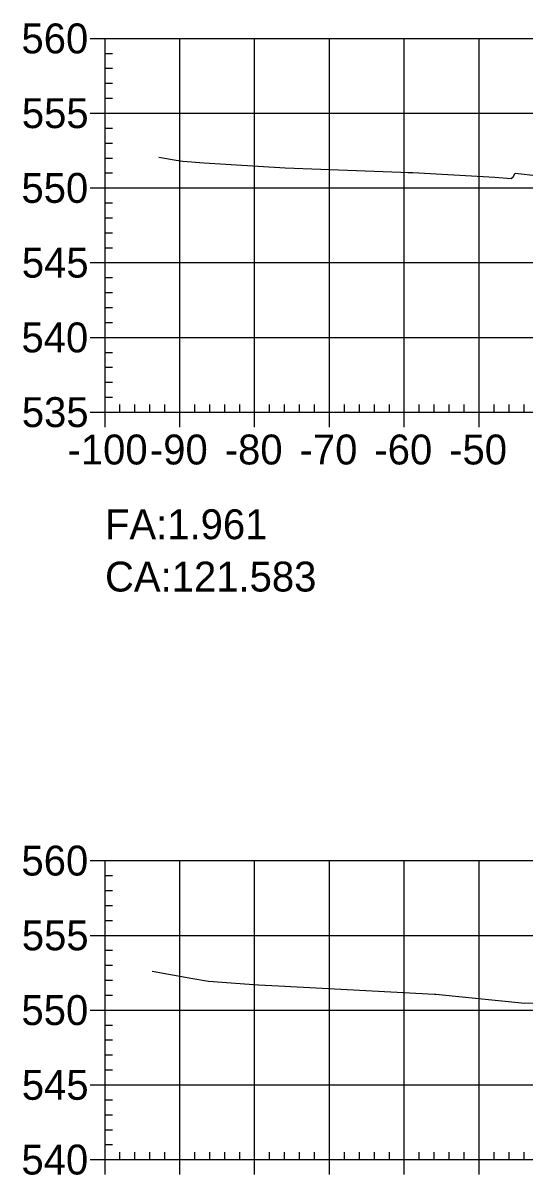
# Model space of a CAD drawing. Extents: x 704834 to 709892, y 372981 to 377533.
# Drawn here: x 707125.9 to 707193, y 373740.8 to 373894.9 of the extents above; entities that cross this region are included whole.
import ezdxf

# ---------------------------------------------------------------- set-up
doc = ezdxf.new("R2010")
doc.units = 0
for name, color, linetype in [('57', 7, 'Continuous'), ('59', 7, 'Continuous'), ('Existing', 7, 'Continuous')]:
    doc.layers.add(name, color=color, linetype=linetype)

msp = doc.modelspace()

# ---------------------------------------------------------------- linework, layer by layer
at = {"layer": '57'}
for p, q in [((707134.87, 373892.82), (707136.87, 373892.82)), ((707136.87, 373892.82), (707336.87, 373892.82)), ((707136.87, 373842.82), (707136.87, 373892.82)), ((707136.87, 373842.82), (707136.87, 373892.82)), ((707146.87, 373842.82), (707146.87, 373892.82)), ((707156.87, 373842.82), (707156.87, 373892.82)), ((707166.87, 373842.82), (707166.87, 373892.82)), ((707176.87, 373842.82), (707176.87, 373892.82)), ((707186.87, 373842.82), (707186.87, 373892.82)), ((707136.87, 373890.82), (707137.87, 373890.82)), ((707136.87, 373888.82), (707137.87, 373888.82)), ((707136.87, 373886.82), (707137.87, 373886.82)), ((707136.87, 373884.82), (707137.87, 373884.82)), ((707134.87, 373882.82), (707136.87, 373882.82)), ((707136.87, 373882.82), (707336.87, 373882.82)), ((707136.87, 373880.82), (707137.87, 373880.82)), ((707136.87, 373878.82), (707137.87, 373878.82)), ((707136.87, 373876.82), (707137.87, 373876.82)), ((707136.87, 373874.82), (707137.87, 373874.82)), ((707134.87, 373872.82), (707136.87, 373872.82)), ((707136.87, 373872.82), (707336.87, 373872.82)), ((707136.87, 373870.82), (707137.87, 373870.82)), ((707136.87, 373868.82), (707137.87, 373868.82)), ((707136.87, 373866.82), (707137.87, 373866.82)), ((707136.87, 373864.82), (707137.87, 373864.82)), ((707134.87, 373862.82), (707136.87, 373862.82)), ((707136.87, 373862.82), (707336.87, 373862.82)), ((707136.87, 373860.82), (707137.87, 373860.82)), ((707136.87, 373858.82), (707137.87, 373858.82)), ((707136.87, 373856.82), (707137.87, 373856.82)), ((707136.87, 373854.82), (707137.87, 373854.82)), ((707134.87, 373852.82), (707136.87, 373852.82)), ((707136.87, 373852.82), (707336.87, 373852.82)), ((707136.87, 373850.82), (707137.87, 373850.82)), ((707136.87, 373848.82), (707137.87, 373848.82)), ((707136.87, 373846.82), (707137.87, 373846.82)), ((707136.87, 373844.82), (707137.87, 373844.82)), ((707138.87, 373842.82), (707138.87, 373843.82)), ((707140.87, 373842.82), (707140.87, 373843.82)), ((707142.87, 373842.82), (707142.87, 373843.82)), ((707144.87, 373842.82), (707144.87, 373843.82)), ((707148.87, 373842.82), (707148.87, 373843.82)), ((707150.87, 373842.82), (707150.87, 373843.82)), ((707152.87, 373842.82), (707152.87, 373843.82)), ((707154.87, 373842.82), (707154.87, 373843.82)), ((707158.87, 373842.82), (707158.87, 373843.82)), ((707160.87, 373842.82), (707160.87, 373843.82)), ((707162.87, 373842.82), (707162.87, 373843.82)), ((707164.87, 373842.82), (707164.87, 373843.82)), ((707168.87, 373842.82), (707168.87, 373843.82)), ((707170.87, 373842.82), (707170.87, 373843.82)), ((707172.87, 373842.82), (707172.87, 373843.82)), ((707174.87, 373842.82), (707174.87, 373843.82)), ((707178.87, 373842.82), (707178.87, 373843.82)), ((707180.87, 373842.82), (707180.87, 373843.82)), ((707182.87, 373842.82), (707182.87, 373843.82)), ((707184.87, 373842.82), (707184.87, 373843.82)), ((707188.87, 373842.82), (707188.87, 373843.82)), ((707190.87, 373842.82), (707190.87, 373843.82)), ((707192.87, 373842.82), (707192.87, 373843.82)), ((707134.87, 373842.82), (707136.87, 373842.82)), ((707136.87, 373842.82), (707336.87, 373842.82)), ((707136.87, 373842.82), (707336.87, 373842.82)), ((707136.87, 373840.82), (707136.87, 373842.82)), ((707146.87, 373840.82), (707146.87, 373842.82)), ((707156.87, 373840.82), (707156.87, 373842.82)), ((707166.87, 373840.82), (707166.87, 373842.82)), ((707176.87, 373840.82), (707176.87, 373842.82)), ((707186.87, 373840.82), (707186.87, 373842.82)), ((707134.87, 373782.82), (707136.87, 373782.82)), ((707136.87, 373782.82), (707336.87, 373782.82)), ((707136.87, 373742.82), (707136.87, 373782.82)), ((707136.87, 373742.82), (707136.87, 373782.82)), ((707146.87, 373742.82), (707146.87, 373782.82)), ((707156.87, 373742.82), (707156.87, 373782.82)), ((707166.87, 373742.82), (707166.87, 373782.82)), ((707176.87, 373742.82), (707176.87, 373782.82)), ((707186.87, 373742.82), (707186.87, 373782.82)), ((707136.87, 373780.82), (707137.87, 373780.82)), ((707136.87, 373778.82), (707137.87, 373778.82)), ((707136.87, 373776.82), (707137.87, 373776.82)), ((707136.87, 373774.82), (707137.87, 373774.82)), ((707134.87, 373772.82), (707136.87, 373772.82)), ((707136.87, 373772.82), (707336.87, 373772.82)), ((707136.87, 373770.82), (707137.87, 373770.82)), ((707136.87, 373768.82), (707137.87, 373768.82)), ((707136.87, 373766.82), (707137.87, 373766.82)), ((707136.87, 373764.82), (707137.87, 373764.82)), ((707134.87, 373762.82), (707136.87, 373762.82)), ((707136.87, 373762.82), (707336.87, 373762.82)), ((707136.87, 373760.82), (707137.87, 373760.82)), ((707136.87, 373758.82), (707137.87, 373758.82)), ((707136.87, 373756.82), (707137.87, 373756.82)), ((707136.87, 373754.82), (707137.87, 373754.82)), ((707134.87, 373752.82), (707136.87, 373752.82)), ((707136.87, 373752.82), (707336.87, 373752.82)), ((707136.87, 373750.82), (707137.87, 373750.82)), ((707136.87, 373748.82), (707137.87, 373748.82)), ((707136.87, 373746.82), (707137.87, 373746.82)), ((707136.87, 373744.82), (707137.87, 373744.82)), ((707138.87, 373742.82), (707138.87, 373743.82)), ((707140.87, 373742.82), (707140.87, 373743.82)), ((707142.87, 373742.82), (707142.87, 373743.82)), ((707144.87, 373742.82), (707144.87, 373743.82)), ((707148.87, 373742.82), (707148.87, 373743.82)), ((707150.87, 373742.82), (707150.87, 373743.82)), ((707152.87, 373742.82), (707152.87, 373743.82)), ((707154.87, 373742.82), (707154.87, 373743.82)), ((707158.87, 373742.82), (707158.87, 373743.82)), ((707160.87, 373742.82), (707160.87, 373743.82)), ((707162.87, 373742.82), (707162.87, 373743.82)), ((707164.87, 373742.82), (707164.87, 373743.82)), ((707168.87, 373742.82), (707168.87, 373743.82)), ((707170.87, 373742.82), (707170.87, 373743.82)), ((707172.87, 373742.82), (707172.87, 373743.82)), ((707174.87, 373742.82), (707174.87, 373743.82)), ((707178.87, 373742.82), (707178.87, 373743.82)), ((707180.87, 373742.82), (707180.87, 373743.82)), ((707182.87, 373742.82), (707182.87, 373743.82)), ((707184.87, 373742.82), (707184.87, 373743.82)), ((707188.87, 373742.82), (707188.87, 373743.82)), ((707190.87, 373742.82), (707190.87, 373743.82)), ((707192.87, 373742.82), (707192.87, 373743.82)), ((707134.87, 373742.82), (707136.87, 373742.82)), ((707136.87, 373742.82), (707336.87, 373742.82)), ((707136.87, 373742.82), (707336.87, 373742.82)), ((707136.87, 373740.82), (707136.87, 373742.82)), ((707146.87, 373740.82), (707146.87, 373742.82)), ((707156.87, 373740.82), (707156.87, 373742.82)), ((707166.87, 373740.82), (707166.87, 373742.82)), ((707176.87, 373740.82), (707176.87, 373742.82)), ((707186.87, 373740.82), (707186.87, 373742.82))]:
    msp.add_line(p, q, dxfattribs=at)
at = {"layer": 'Existing'}
for points in [[(707144.08, 373876.94), (707146.38, 373876.52), (707147.27, 373876.38), (707150.1, 373876.17), (707160.96, 373875.49), (707176.4, 373874.94), (707177.33, 373874.89), (707178, 373874.86), (707188.97, 373874.26), (707191.17, 373874.09), (707191.43, 373874.28), (707191.67, 373874.77), (707194.85, 373874.43)], [(707143.17, 373768.03), (707148.59, 373767.04), (707150.68, 373766.71), (707157.33, 373766.22), (707157.34, 373766.22), (707157.37, 373766.22), (707160.06, 373766.08), (707180.89, 373764.97), (707181.08, 373764.96), (707192.99, 373763.73), (707194.1, 373763.77)]]:
    msp.add_lwpolyline(points, dxfattribs=at)

# ---------------------------------------------------------------- texts
msp.add_text('CA:121.583', height=4).set_placement((707136.87, 373818.82))
at = {"layer": '57'}
for s, p in [('560', (707125.7, 373890.82)), ('555', (707125.75, 373880.82)), ('550', (707125.7, 373870.82)), ('545', (707125.75, 373860.82)), ('540', (707125.7, 373850.82)), ('535', (707125.75, 373840.82)), ('-100', (707131.86, 373835.82)), ('-90', (707142.87, 373835.82)), ('-80', (707152.87, 373835.82)), ('-70', (707162.87, 373835.82)), ('-60', (707172.87, 373835.82)), ('-50', (707182.87, 373835.82)), ('560', (707125.7, 373780.82)), ('555', (707125.75, 373770.82)), ('550', (707125.7, 373760.82)), ('545', (707125.75, 373750.82)), ('540', (707125.7, 373740.82))]:
    msp.add_text(s, height=4, dxfattribs=at).set_placement(p)
at = {"layer": '59'}
msp.add_text('FA:1.961', height=4, dxfattribs=at).set_placement((707136.87, 373825.82))

doc.saveas('drawing.dxf')
